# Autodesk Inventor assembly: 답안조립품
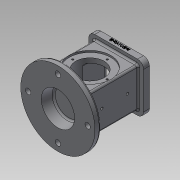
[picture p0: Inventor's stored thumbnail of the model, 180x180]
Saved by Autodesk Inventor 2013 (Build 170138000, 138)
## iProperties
Created: 2018-10
Part Number: 답안조립품
Document SubType Name: Assembly
Designer: Administrator
Author: Administrator
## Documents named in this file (2)
- C:\Documents and Settings\Administrator\바탕 화면\481007V1043\답안조립품.iam
- C:\Documents and Settings\Administrator\바탕 화면\481007V1043\본체.ipt
